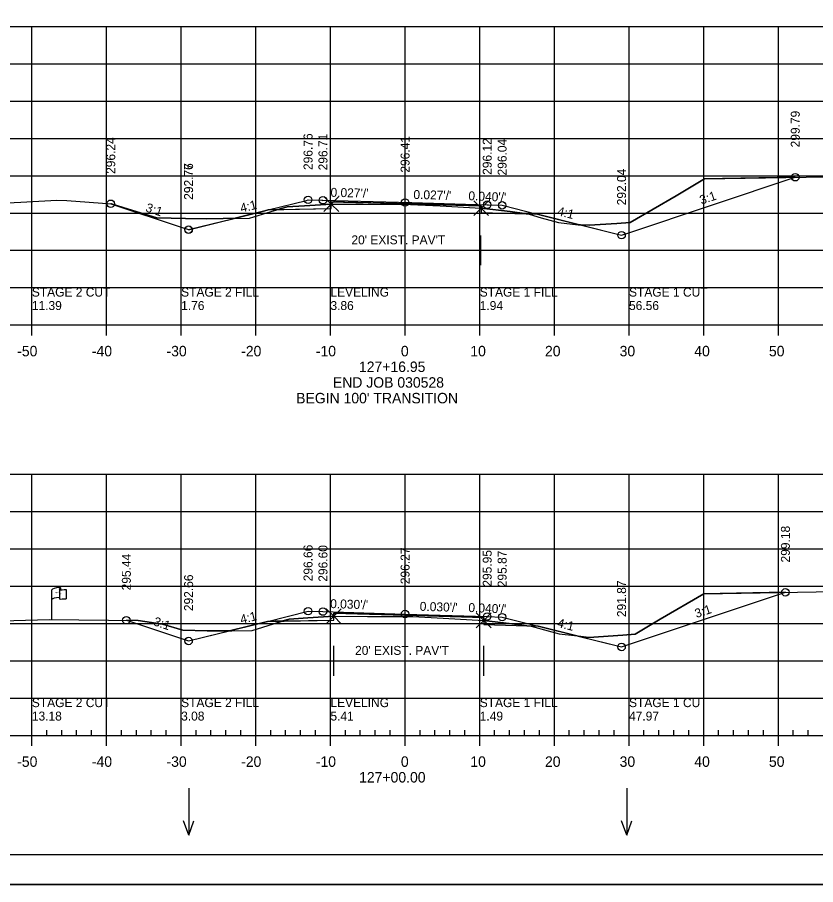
# Model space of a CAD drawing. Extents: x 1370843 to 1371177, y 380307 to 382654.
# Drawn here: x 1370961.8 to 1371068.7, y 382440.8 to 382557 of the extents above; entities that cross this region are included whole.
import ezdxf

# ---------------------------------------------------------------- set-up
doc = ezdxf.new("R2010")
doc.units = 0
for name, color, linetype in [('R_Alt Surface', 7, 'Continuous'), ('R_Axis', 7, 'Continuous'), ('R_Axis Annot', 7, 'Continuous'), ('R_Border', 7, 'Continuous'), ('R_Exist Surface', 7, 'Continuous'), ('R_Exist Surface Annot', 7, 'Continuous'), ('R_Fin Surface', 7, 'Continuous'), ('R_Fin Surface Annot', 7, 'Continuous'), ('R_Grid', 7, 'Continuous'), ('R_No Plot', 7, 'Continuous'), ('R_ROW', 7, 'Continuous'), ('R_Water Annot', 7, 'Continuous')]:
    doc.layers.add(name, color=color, linetype=linetype)

msp = doc.modelspace()

# ---------------------------------------------------------------- linework, layer by layer
at = {"layer": 'R_Alt Surface'}
for points in [[(1370995.36, 382531.25), (1371003.83, 382531.42), (1371003.83, 382532.34), (1371013.71, 382532.07), (1371023.9, 382531.8), (1371023.9, 382530.88), (1371031.45, 382530.68)], [(1370995.26, 382476.12), (1371004.15, 382476.3), (1371004.15, 382477.22), (1371013.71, 382476.93), (1371024.24, 382476.62), (1371024.24, 382475.71), (1371031.54, 382475.49)]]:
    msp.add_lwpolyline(points, dxfattribs=at)
at = {"layer": 'R_Axis'}
for p, q in [((1370868.71, 382515.83), (1371158.71, 382515.83)), ((1370963.71, 382514.43), (1370963.71, 382515.83)), ((1370973.71, 382514.43), (1370973.71, 382515.83)), ((1370983.71, 382514.43), (1370983.71, 382515.83)), ((1370993.71, 382514.43), (1370993.71, 382515.83)), ((1371003.71, 382514.43), (1371003.71, 382515.83)), ((1371013.71, 382514.43), (1371013.71, 382515.83)), ((1371023.71, 382514.43), (1371023.71, 382515.83)), ((1371033.71, 382514.43), (1371033.71, 382515.83)), ((1371043.71, 382514.43), (1371043.71, 382515.83)), ((1371053.71, 382514.43), (1371053.71, 382515.83)), ((1371063.71, 382514.43), (1371063.71, 382515.83)), ((1370868.71, 382460.83), (1371158.71, 382460.83)), ((1370963.71, 382459.43), (1370963.71, 382460.83)), ((1370965.71, 382460.83), (1370965.71, 382461.53)), ((1370967.71, 382460.83), (1370967.71, 382461.53)), ((1370969.71, 382460.83), (1370969.71, 382461.53)), ((1370971.71, 382460.83), (1370971.71, 382461.53)), ((1370973.71, 382459.43), (1370973.71, 382460.83)), ((1370975.71, 382460.83), (1370975.71, 382461.53)), ((1370977.71, 382460.83), (1370977.71, 382461.53)), ((1370979.71, 382460.83), (1370979.71, 382461.53)), ((1370981.71, 382460.83), (1370981.71, 382461.53)), ((1370983.71, 382459.43), (1370983.71, 382460.83)), ((1370985.71, 382460.83), (1370985.71, 382461.53)), ((1370987.71, 382460.83), (1370987.71, 382461.53)), ((1370989.71, 382460.83), (1370989.71, 382461.53)), ((1370991.71, 382460.83), (1370991.71, 382461.53)), ((1370993.71, 382459.43), (1370993.71, 382460.83)), ((1370995.71, 382460.83), (1370995.71, 382461.53)), ((1370997.71, 382460.83), (1370997.71, 382461.53)), ((1370999.71, 382460.83), (1370999.71, 382461.53)), ((1371001.71, 382460.83), (1371001.71, 382461.53)), ((1371003.71, 382459.43), (1371003.71, 382460.83)), ((1371005.71, 382460.83), (1371005.71, 382461.53)), ((1371007.71, 382460.83), (1371007.71, 382461.53)), ((1371009.71, 382460.83), (1371009.71, 382461.53)), ((1371011.71, 382460.83), (1371011.71, 382461.53)), ((1371013.71, 382459.43), (1371013.71, 382460.83)), ((1371015.71, 382460.83), (1371015.71, 382461.53)), ((1371017.71, 382460.83), (1371017.71, 382461.53)), ((1371019.71, 382460.83), (1371019.71, 382461.53)), ((1371021.71, 382460.83), (1371021.71, 382461.53)), ((1371023.71, 382459.43), (1371023.71, 382460.83)), ((1371025.71, 382460.83), (1371025.71, 382461.53)), ((1371027.71, 382460.83), (1371027.71, 382461.53)), ((1371029.71, 382460.83), (1371029.71, 382461.53)), ((1371031.71, 382460.83), (1371031.71, 382461.53)), ((1371033.71, 382459.43), (1371033.71, 382460.83)), ((1371035.71, 382460.83), (1371035.71, 382461.53)), ((1371037.71, 382460.83), (1371037.71, 382461.53)), ((1371039.71, 382460.83), (1371039.71, 382461.53)), ((1371041.71, 382460.83), (1371041.71, 382461.53)), ((1371043.71, 382459.43), (1371043.71, 382460.83)), ((1371045.71, 382460.83), (1371045.71, 382461.53)), ((1371047.71, 382460.83), (1371047.71, 382461.53)), ((1371049.71, 382460.83), (1371049.71, 382461.53)), ((1371051.71, 382460.83), (1371051.71, 382461.53)), ((1371053.71, 382459.43), (1371053.71, 382460.83)), ((1371055.71, 382460.83), (1371055.71, 382461.53)), ((1371057.71, 382460.83), (1371057.71, 382461.53)), ((1371059.71, 382460.83), (1371059.71, 382461.53)), ((1371061.71, 382460.83), (1371061.71, 382461.53)), ((1371063.71, 382459.43), (1371063.71, 382460.83)), ((1371065.71, 382460.83), (1371065.71, 382461.53)), ((1371067.71, 382460.83), (1371067.71, 382461.53))]:
    msp.add_line(p, q, dxfattribs=at)
at = {"layer": 'R_Border'}
msp.add_line((1371171.89, 382444.83), (1370855.71, 382444.83), dxfattribs=at)
at = {"layer": 'R_Exist Surface'}
for points in [[(1370934.56, 382530.9), (1370962.22, 382532.28), (1370967.08, 382532.54), (1370968.38, 382532.51), (1370974.39, 382532.06), (1370977.34, 382531.13), (1370980.46, 382530.17), (1370984.31, 382530.08), (1370987.06, 382530.03), (1370989.33, 382530.08), (1370992.87, 382530.12), (1370995.79, 382531.03), (1370997.9, 382531.64), (1371000.22, 382531.8), (1371003.83, 382532.02), (1371008.08, 382532.01), (1371014.45, 382531.99), (1371018.41, 382531.77), (1371023.9, 382531.48), (1371027.78, 382531.01), (1371030.34, 382530.68), (1371031.94, 382530.17), (1371034.26, 382529.57), (1371036.9, 382529.26), (1371038.37, 382529.18), (1371042.06, 382529.44), (1371043.86, 382529.57), (1371050.04, 382533.14), (1371053.83, 382535.42), (1371070.15, 382535.69)], [(1370935.98, 382475.53), (1370966.04, 382476.39), (1370977.96, 382476.25), (1370981.22, 382475.75), (1370983.92, 382474.92), (1370987.19, 382474.84), (1370990.48, 382474.86), (1370993.22, 382474.89), (1370996.09, 382475.77), (1370998.19, 382476.43), (1371000.67, 382476.58), (1371004.15, 382476.8), (1371008.67, 382476.78), (1371014.77, 382476.76), (1371018.81, 382476.55), (1371024.24, 382476.25), (1371028.01, 382475.78), (1371030.6, 382475.46), (1371032.89, 382474.83), (1371034.35, 382474.45), (1371036.81, 382474.16), (1371038.33, 382473.98), (1371042.9, 382474.27), (1371044.54, 382474.39), (1371047.9, 382476.43), (1371053.73, 382479.82), (1371078.82, 382480.25)]]:
    msp.add_lwpolyline(points, dxfattribs=at)
at = {"layer": 'R_Exist Surface Annot'}
for p, q in [((1371003.71, 382523.83), (1371003.71, 382527.83)), ((1371023.86, 382523.83), (1371023.86, 382527.83)), ((1371003.71, 382525.83), (1371023.86, 382525.83)), ((1371004.15, 382468.83), (1371004.15, 382472.83)), ((1371024.24, 382468.83), (1371024.24, 382472.83)), ((1371004.15, 382470.83), (1371024.24, 382470.83))]:
    msp.add_line(p, q, dxfattribs=at)
at = {"layer": 'R_Fin Surface'}
for points in [[(1370974.29, 382532.07), (1370983.86, 382528.88), (1370984.7, 382528.6), (1370984.71, 382528.59), (1370984.71, 382528.59), (1370994.91, 382531.11), (1370995.36, 382531.25), (1370995.36, 382531.25), (1371000.52, 382532.51), (1371000.71, 382532.59), (1371000.71, 382532.59), (1371002.55, 382532.54), (1371002.63, 382532.51), (1371002.71, 382532.54), (1371002.71, 382532.54), (1371012.82, 382532.27), (1371013.25, 382532.23), (1371013.71, 382532.24), (1371014.17, 382532.23), (1371014.6, 382532.22), (1371024.71, 382531.94), (1371024.71, 382531.94), (1371024.79, 382531.94), (1371024.87, 382531.94), (1371026.71, 382531.86), (1371026.71, 382531.86), (1371026.9, 382531.82), (1371031.23, 382530.73), (1371031.25, 382530.73), (1371031.44, 382530.68), (1371031.45, 382530.68), (1371031.93, 382530.56), (1371042.71, 382527.86), (1371042.71, 382527.86), (1371043.69, 382528.19), (1371065.98, 382535.62), (1371065.98, 382535.62)], [(1370976.37, 382476.27), (1370984.7, 382473.49), (1370984.71, 382473.49), (1370995.26, 382476.12), (1371000.71, 382477.49), (1371002.71, 382477.43), (1371013.71, 382477.1), (1371024.71, 382476.77), (1371026.71, 382476.69), (1371031.54, 382475.49), (1371042.71, 382472.69), (1371064.66, 382480.01)]]:
    msp.add_lwpolyline(points, dxfattribs=at)
at = {"layer": 'R_Grid'}
for p, q in [((1370868.71, 382555.83), (1371158.71, 382555.83)), ((1370963.71, 382515.83), (1370963.71, 382555.83)), ((1370973.71, 382515.83), (1370973.71, 382555.83)), ((1370983.71, 382515.83), (1370983.71, 382555.83)), ((1370993.71, 382515.83), (1370993.71, 382555.83)), ((1371003.71, 382515.83), (1371003.71, 382555.83)), ((1371013.71, 382515.83), (1371013.71, 382555.83)), ((1371023.71, 382515.83), (1371023.71, 382555.83)), ((1371033.71, 382515.83), (1371033.71, 382555.83)), ((1371043.71, 382515.83), (1371043.71, 382555.83)), ((1371053.71, 382515.83), (1371053.71, 382555.83)), ((1371063.71, 382515.83), (1371063.71, 382555.83)), ((1370868.71, 382550.83), (1371158.71, 382550.83)), ((1370868.71, 382545.83), (1371158.71, 382545.83)), ((1370868.71, 382540.83), (1371158.71, 382540.83)), ((1370868.71, 382535.83), (1371158.71, 382535.83)), ((1370868.71, 382530.83), (1371158.71, 382530.83)), ((1370868.71, 382525.83), (1371158.71, 382525.83)), ((1370868.71, 382520.83), (1371158.71, 382520.83)), ((1370868.71, 382515.83), (1371158.71, 382515.83)), ((1370868.71, 382495.83), (1371158.71, 382495.83)), ((1370963.71, 382460.83), (1370963.71, 382495.83)), ((1370973.71, 382460.83), (1370973.71, 382495.83)), ((1370983.71, 382460.83), (1370983.71, 382495.83)), ((1370993.71, 382460.83), (1370993.71, 382495.83)), ((1371003.71, 382460.83), (1371003.71, 382495.83)), ((1371013.71, 382460.83), (1371013.71, 382495.83)), ((1371023.71, 382460.83), (1371023.71, 382495.83)), ((1371033.71, 382460.83), (1371033.71, 382495.83)), ((1371043.71, 382460.83), (1371043.71, 382495.83)), ((1371053.71, 382460.83), (1371053.71, 382495.83)), ((1371063.71, 382460.83), (1371063.71, 382495.83)), ((1370868.71, 382490.83), (1371158.71, 382490.83)), ((1370868.71, 382485.83), (1371158.71, 382485.83)), ((1370868.71, 382480.83), (1371158.71, 382480.83)), ((1370868.71, 382475.83), (1371158.71, 382475.83)), ((1370868.71, 382470.83), (1371158.71, 382470.83)), ((1370868.71, 382465.83), (1371158.71, 382465.83)), ((1370868.71, 382460.83), (1371158.71, 382460.83))]:
    msp.add_line(p, q, dxfattribs=at)
at = {"layer": 'R_No Plot'}
for p, q in [((1371003.83, 382531.42), (1371003.83, 382532.02)), ((1371023.9, 382531.48), (1371023.9, 382531.8)), ((1370996.66, 382531.28), (1370995.36, 382531.25)), ((1370996.66, 382531.28), (1371003.83, 382531.42)), ((1371023.9, 382531.48), (1371023.9, 382530.88)), ((1371023.9, 382530.88), (1371030.02, 382530.72)), ((1370979.54, 382530.32), (1370983.86, 382528.88)), ((1371037.2, 382529.24), (1371042.71, 382527.86)), ((1370843.31, 382440.85), (1371176.64, 382440.85))]:
    msp.add_line(p, q, dxfattribs=at)
for points in [[(1370843.3, 382654.18), (1371176.64, 382654.18), (1371176.64, 382440.85), (1370843.3, 382440.85)], [(1371089.63, 382650.29), (1371089.63, 382640.41), (1371125.36, 382640.41), (1371125.36, 382637.49), (1371148.56, 382637.49), (1371148.56, 382613.16), (1371171.89, 382613.16), (1371171.89, 382444.83), (1370855.71, 382444.83), (1370855.71, 382650.29)], [(1371036.89, 382474.15), (1371042.71, 382472.69), (1371064.66, 382480.01), (1371053.73, 382479.82), (1371047.9, 382476.43), (1371044.54, 382474.39), (1371042.9, 382474.27), (1371038.33, 382473.98)], [(1371004.15, 382476.8), (1371008.67, 382476.78), (1371014.77, 382476.76), (1371018.81, 382476.55), (1371024.24, 382476.25), (1371024.24, 382476.62), (1371013.71, 382476.93), (1371004.15, 382477.22)], [(1370976.37, 382476.27), (1370984.7, 382473.49), (1370990.21, 382474.86), (1370987.19, 382474.84), (1370983.92, 382474.92), (1370981.22, 382475.75), (1370977.96, 382476.25)], [(1370990.21, 382474.86), (1370990.48, 382474.86), (1370993.22, 382474.89), (1370996.09, 382475.77), (1370997.35, 382476.17), (1370995.26, 382476.12)], [(1370997.35, 382476.17), (1371004.15, 382476.3), (1371004.15, 382476.8), (1371000.67, 382476.58), (1370998.19, 382476.43)], [(1371024.24, 382476.25), (1371024.24, 382475.71), (1371030.04, 382475.53), (1371028.01, 382475.78)], [(1371030.04, 382475.53), (1371030.6, 382475.46), (1371032.89, 382474.83), (1371034.35, 382474.45), (1371036.81, 382474.16), (1371036.89, 382474.15), (1371031.54, 382475.49)]]:
    msp.add_lwpolyline(points, close=True, dxfattribs=at)
for points in [[(1371065.98, 382535.62), (1371053.83, 382535.42), (1371050.04, 382533.14), (1371043.86, 382529.57), (1371042.06, 382529.44), (1371038.37, 382529.18), (1371037.2, 382529.24)], [(1371042.71, 382527.86), (1371043.69, 382528.19), (1371065.98, 382535.62)], [(1371065.98, 382535.62), (1371065.98, 382535.62)], [(1371003.83, 382532.02), (1371002.83, 382533.02), (1371003.83, 382532.02), (1371002.83, 382531.02), (1371003.83, 382532.02), (1371004.83, 382531.02), (1371003.83, 382532.02), (1371004.83, 382533.02)], [(1370980.46, 382530.17), (1370976.68, 382531.34), (1370974.39, 382532.06), (1370974.29, 382532.07), (1370979.54, 382530.32)], [(1371003.83, 382532.02), (1371000.22, 382531.8), (1370997.9, 382531.64), (1370996.66, 382531.28)], [(1371014.49, 382532.05), (1371003.83, 382532.34)], [(1371003.83, 382532.34), (1371003.83, 382532.02)], [(1371003.83, 382532.02), (1371008.08, 382532.01), (1371014.45, 382531.99), (1371018.41, 382531.77), (1371023.9, 382531.48)], [(1371023.9, 382531.8), (1371014.49, 382532.05)], [(1371023.9, 382531.48), (1371022.9, 382532.48), (1371023.9, 382531.48), (1371022.9, 382530.48), (1371023.9, 382531.48), (1371024.9, 382530.48), (1371023.9, 382531.48), (1371024.9, 382532.48)], [(1370990.79, 382530.1), (1370992.87, 382530.12), (1370995.79, 382531.03), (1370996.66, 382531.28)], [(1370995.36, 382531.25), (1370994.91, 382531.11), (1370990.79, 382530.1)], [(1371030.02, 382530.72), (1371027.78, 382531.01), (1371023.9, 382531.48)], [(1371030.34, 382530.71), (1371030.02, 382530.72), (1371030.34, 382530.68)], [(1371031.44, 382530.68), (1371031.23, 382530.69), (1371030.34, 382530.71)], [(1371030.34, 382530.68), (1371031.94, 382530.17), (1371034.26, 382529.57), (1371036.9, 382529.26)], [(1371036.91, 382529.31), (1371031.93, 382530.56), (1371031.44, 382530.68)], [(1370990.79, 382530.1), (1370989.33, 382530.08), (1370987.06, 382530.03), (1370984.31, 382530.08), (1370980.46, 382530.17)], [(1370983.86, 382528.88), (1370984.7, 382528.6), (1370990.79, 382530.1)], [(1371036.9, 382529.26), (1371037.2, 382529.24), (1371036.91, 382529.31)], [(1371004.15, 382476.8), (1371003.15, 382477.8), (1371004.15, 382476.8), (1371003.15, 382475.8), (1371004.15, 382476.8), (1371005.15, 382475.8), (1371004.15, 382476.8), (1371005.15, 382477.8)], [(1371024.24, 382476.25), (1371023.24, 382477.25), (1371024.24, 382476.25), (1371023.24, 382475.25), (1371024.24, 382476.25), (1371025.24, 382475.25), (1371024.24, 382476.25), (1371025.24, 382477.25)]]:
    msp.add_lwpolyline(points, dxfattribs=at)
for centre in [(1371065.98, 382535.62), (1371000.71, 382532.59), (1371002.71, 382532.54), (1371013.71, 382532.24), (1370974.28, 382532.07), (1371024.71, 382531.94), (1371026.71, 382531.86), (1370984.7, 382528.6), (1370984.71, 382528.59), (1371042.71, 382527.86), (1371064.66, 382480.01), (1371000.71, 382477.49), (1371002.71, 382477.43), (1371013.71, 382477.1), (1371024.71, 382476.77), (1371026.71, 382476.69), (1370976.37, 382476.27), (1370984.71, 382473.49), (1371042.71, 382472.69)]:
    msp.add_circle(centre, 0.5, dxfattribs=at)
at = {"layer": 'R_ROW'}
for p, q in [((1370967.4, 382480.43), (1370967.4, 382480.42)), ((1370967.4, 382480.42), (1370967.4, 382479.19)), ((1370967.56, 382480.59), (1370967.56, 382480.35)), ((1370968.33, 382480.39), (1370968.33, 382479.15)), ((1370966.4, 382476.39), (1370966.4, 382480.34))]:
    msp.add_line(p, q, dxfattribs=at)
for centre, radius, start, end in [((1370967.47, 382480.43), 0.078, 88.6458, 274.2828), ((1370967.48, 382480.59), 0.0783, 263.0712, 93.9564), ((1370967.47, 382479.19), 0.0783, 180, 273.9564)]:
    msp.add_arc(centre, radius, start, end, dxfattribs=at)
for centre, major_axis, ratio, start_param, end_param in [((1370967.98, 382480.38), (-1.58, -0.04), 0.19887, 5.030368, 6.283185), ((1370968.69, 382480.5), (-1.23, -0.13), 0.052933, 0.159456, 1.268315), ((1370967.98, 382479.06), (-1.58, -0.04), 0.19887, 5.083035, 6.194897), ((1370968.69, 382479.26), (-1.23, -0.13), 0.052933, 0.159456, 1.268315)]:
    msp.add_ellipse(centre, major_axis=major_axis, ratio=ratio, start_param=start_param, end_param=end_param, dxfattribs=at)
at = {"layer": 'R_Water Annot'}
for p, q in [((1370984.73, 382453.75), (1370984.73, 382447.47)), ((1371043.4, 382453.75), (1371043.4, 382447.47)), ((1370984.73, 382447.47), (1370984.03, 382449.39)), ((1370984.73, 382447.47), (1370985.43, 382449.39)), ((1371043.4, 382447.47), (1371042.7, 382449.39)), ((1371043.4, 382447.47), (1371044.1, 382449.39))]:
    msp.add_line(p, q, dxfattribs=at)

# ---------------------------------------------------------------- texts
at = {"layer": 'R_Axis Annot'}
for s, p in [('-50', (1370961.75, 382511.63)), ('-40', (1370971.75, 382511.63)), ('-30', (1370981.75, 382511.63)), ('-20', (1370991.75, 382511.63)), ('-10', (1371001.75, 382511.63)), ('0', (1371013.15, 382511.63)), ('10', (1371022.45, 382511.63)), ('20', (1371032.45, 382511.63)), ('30', (1371042.45, 382511.63)), ('40', (1371052.45, 382511.63)), ('50', (1371062.45, 382511.63)), ('127+16.95', (1371007.53, 382509.53)), ('END JOB 030528', (1371004.04, 382507.43)), ("BEGIN 100' TRANSITION", (1370999.12, 382505.33)), ('-50', (1370961.75, 382456.63)), ('-40', (1370971.75, 382456.63)), ('-30', (1370981.75, 382456.63)), ('-20', (1370991.75, 382456.63)), ('-10', (1371001.75, 382456.63)), ('0', (1371013.15, 382456.63)), ('10', (1371022.45, 382456.63)), ('20', (1371032.45, 382456.63)), ('30', (1371042.45, 382456.63)), ('40', (1371052.45, 382456.63)), ('50', (1371062.45, 382456.63)), ('127+00.00', (1371007.55, 382454.53))]:
    msp.add_text(s, height=1.4, dxfattribs=at).set_placement(p)
at = {"layer": 'R_Exist Surface Annot'}
for p in [(1371006.52, 382526.63), (1371007.01, 382471.63)]:
    msp.add_text("20' EXIST. PAV'T", height=1.2, dxfattribs=at).set_placement(p)
at = {"layer": 'R_Fin Surface Annot'}
for s, rotation, p in [('299.79', 90, (1371066.58, 382539.62)), ('296.24', 90, (1370974.88, 382536.07)), ('296.76', 90, (1371001.31, 382536.59)), ('296.71', 90, (1371003.31, 382536.54)), ('296.41', 90, (1371014.31, 382536.24)), ('296.12', 90, (1371025.31, 382535.94)), ('296.04', 90, (1371027.31, 382535.86)), ('292.77', 90, (1370985.3, 382532.6)), ('292.76', 90, (1370985.31, 382532.59)), ('292.04', 90, (1371043.31, 382531.86)), ("0.027'/'", 358.4533, (1371003.71, 382533.01)), ("0.027'/'", 358.4533, (1371014.81, 382532.72)), ("0.040'/'", 357.7094, (1371022.17, 382532.55)), ('3:1', 18.4349, (1371053.4, 382531.95)), ('3:1', 341.5651, (1370978.86, 382531.07)), ('4:1', 14.0362, (1370991.78, 382530.88)), ('4:1', 345.9638, (1371034.02, 382530.55)), ('299.18', 90, (1371065.26, 382484.01)), ('296.66', 90, (1371001.31, 382481.49)), ('296.60', 90, (1371003.31, 382481.43)), ('295.44', 90, (1370976.97, 382480.27)), ('296.27', 90, (1371014.31, 382481.1)), ('295.95', 90, (1371025.31, 382480.77)), ('295.87', 90, (1371027.31, 382480.69)), ('292.66', 90, (1370985.31, 382477.49)), ('291.87', 90, (1371043.31, 382476.69)), ("0.030'/'", 358.298, (1371003.66, 382477.9)), ("0.030'/'", 358.298, (1371015.66, 382477.54)), ("0.040'/'", 357.7094, (1371022.17, 382477.38)), ('3:1', 18.4349, (1371052.74, 382476.56)), ('4:1', 14.0362, (1370991.78, 382475.77)), ('3:1', 341.5651, (1370979.91, 382475.62)), ('4:1', 345.9638, (1371034.02, 382475.38))]:
    msp.add_text(s, height=1.2, rotation=rotation, dxfattribs=at).set_placement(p)
at = {"layer": 'R_No Plot'}
for s, p in [('STAGE 2 CUT', (1370963.71, 382519.63)), ('STAGE 2 FILL', (1370983.71, 382519.63)), ('LEVELING', (1371003.71, 382519.63)), ('STAGE 1 FILL', (1371023.71, 382519.63)), ('STAGE 1 CUT', (1371043.71, 382519.63)), ('11.39', (1370963.71, 382517.83)), ('1.76', (1370983.71, 382517.83)), ('3.86', (1371003.71, 382517.83)), ('1.94', (1371023.71, 382517.83)), ('56.56', (1371043.71, 382517.83)), ('STAGE 2 CUT', (1370963.71, 382464.63)), ('STAGE 2 FILL', (1370983.71, 382464.63)), ('LEVELING', (1371003.71, 382464.63)), ('STAGE 1 FILL', (1371023.71, 382464.63)), ('STAGE 1 CUT', (1371043.71, 382464.63)), ('13.18', (1370963.71, 382462.83)), ('3.08', (1370983.71, 382462.83)), ('5.41', (1371003.71, 382462.83)), ('1.49', (1371023.71, 382462.83)), ('47.97', (1371043.71, 382462.83))]:
    msp.add_text(s, height=1.2, dxfattribs=at).set_placement(p)
at = {"layer": 'R_ROW'}
for s, height, rotation, p in [('R ', 0.2, 9.9884, (1370966.92, 382479.84)), (' O', 0.2, 9.9884, (1370967.07, 382479.88)), ('W', 0.2, 351.1788, (1370967.39, 382479.71)), ('DWB 11-9-07', 0.001, 90, (1370967.56, 382480.35)), ('DWB 11-9-07', 0.001, 5.0717, (1370968.32, 382479.15)), ('DWB 11-9-07', 0.001, 90, (1370966.4, 382476.39))]:
    msp.add_text(s, height=height, rotation=rotation, dxfattribs=at).set_placement(p)

doc.saveas('drawing.dxf')
